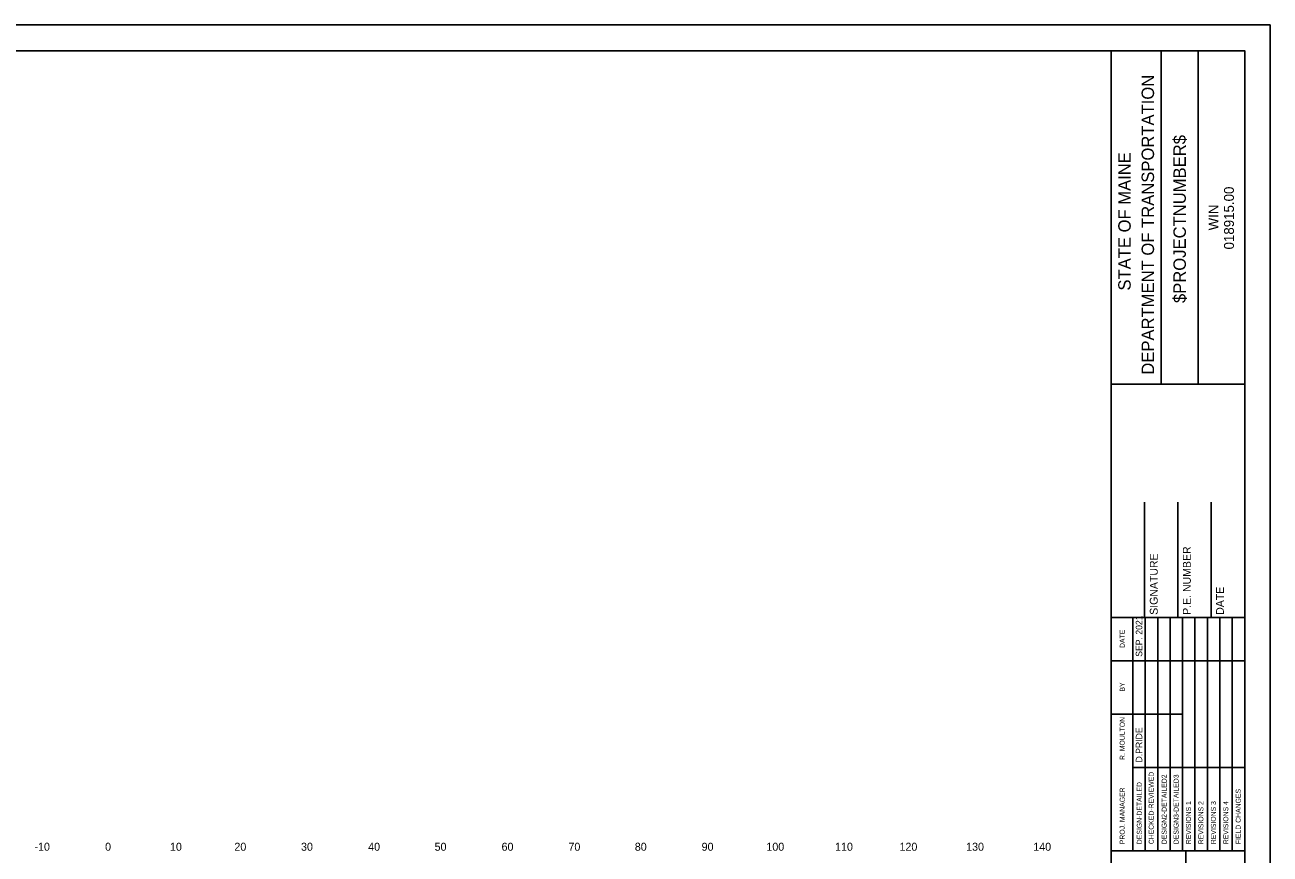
# Model space of a CAD drawing. Extents: x 1686373 to 1686716, y 461260 to 461480.
# Drawn here: x 1686526.3 to 1686713, y 461355.6 to 461480 of the extents above; entities that cross this region are included whole.
import ezdxf

# ---------------------------------------------------------------- set-up
doc = ezdxf.new("R2010")
doc.units = 0
for name, color, linetype in [('BORDER', 7, 'Continuous'), ('H_V ANNOTATION', 7, 'Continuous'), ('PLOT BOUNDARY', 7, 'Continuous')]:
    doc.layers.add(name, color=color, linetype=linetype)

msp = doc.modelspace()

# ---------------------------------------------------------------- linework, layer by layer
at = {"layer": 'BORDER'}
for p, q in [((1686689.17, 461266.07), (1686689.17, 461476.07)), ((1686696.63, 461426.07), (1686696.63, 461476.07)), ((1686702.22, 461426.07), (1686702.22, 461476.07)), ((1686689.17, 461426.06), (1686709.17, 461426.06)), ((1686694.17, 461391.08), (1686694.17, 461408.37)), ((1686699.17, 461391.08), (1686699.17, 461408.37)), ((1686704.17, 461391.08), (1686704.17, 461408.37)), ((1686689.17, 461391.08), (1686709.17, 461391.08)), ((1686689.17, 461356.08), (1686709.17, 461356.08)), ((1686700.35, 461286.08), (1686700.35, 461356.08))]:
    msp.add_line(p, q, dxfattribs=at)
msp.add_lwpolyline([(1686389.17, 461266.07), (1686709.17, 461266.07), (1686709.17, 461476.07), (1686389.17, 461476.07)], close=True, dxfattribs=at)
for points in [[(1686692.4, 461384.58), (1686692.4, 461391.08)], [(1686692.4, 461356.08), (1686692.4, 461389.67)], [(1686694.26, 461356.08), (1686694.26, 461391.08)], [(1686696.13, 461391.08), (1686696.13, 461356.08)], [(1686697.99, 461356.08), (1686697.99, 461391.08)], [(1686699.85, 461356.08), (1686699.85, 461391.08)], [(1686701.72, 461356.08), (1686701.72, 461391.08)], [(1686703.58, 461356.08), (1686703.58, 461391.08)], [(1686705.44, 461356.08), (1686705.44, 461391.08)], [(1686707.31, 461356.08), (1686707.31, 461391.08)], [(1686689.17, 461384.58), (1686709.17, 461384.58)], [(1686689.17, 461376.58), (1686692.4, 461376.58)], [(1686692.4, 461376.58), (1686699.85, 461376.58)], [(1686692.4, 461368.58), (1686709.17, 461368.58)]]:
    msp.add_lwpolyline(points, dxfattribs=at)
at = {"layer": 'PLOT BOUNDARY'}
msp.add_lwpolyline([(1686372.98, 461259.95), (1686712.98, 461259.95), (1686712.98, 461479.95), (1686372.98, 461479.95)], close=True, dxfattribs=at)

# ---------------------------------------------------------------- texts
at = {"layer": 'BORDER'}
for s, height, p in [('DEPARTMENT OF TRANSPORTATION', 1.8635, (1686695.58, 461427.48)), ('$PROJECTNUMBER$', 1.8635, (1686700.35, 461438.23)), ('STATE OF MAINE', 1.8635, (1686692.08, 461440.1)), ('018915.00', 1.491, (1686707.56, 461446.27)), ('WIN', 1.491, (1686705.24, 461449.13)), ('P.E. NUMBER', 1.1811, (1686701.09, 461391.46)), ('SIGNATURE', 1.181, (1686696.13, 461391.46)), ('DATE', 1.181, (1686706.05, 461391.46)), ('SEP. 2021', 0.969, (1686693.81, 461385.17)), ('DATE', 0.743, (1686691.18, 461386.49)), ('BY', 0.743, (1686691.18, 461379.95)), ('R. MOULTON', 0.745, (1686691.18, 461369.68)), ('D.PRIDE', 0.969, (1686693.81, 461369.32)), ('CHECKED-REVIEWED', 0.7455, (1686695.53, 461357.05)), ('DESIGN2-DETAILED2', 0.7455, (1686697.47, 461357.05)), ('DESIGN3-DETAILED3', 0.7455, (1686699.26, 461357.05)), ('PROJ. MANAGER', 0.7455, (1686691.18, 461357.05)), ('DESIGN-DETAILED', 0.7455, (1686693.74, 461357.05)), ('FIELD CHANGES', 0.7455, (1686708.57, 461357.05)), ('REVISIONS 1', 0.7455, (1686701.12, 461357.05)), ('REVISIONS 2', 0.7455, (1686702.98, 461357.05)), ('REVISIONS 3', 0.7455, (1686704.85, 461357.05)), ('REVISIONS 4', 0.7455, (1686706.71, 461357.05))]:
    msp.add_text(s, height=height, rotation=90, dxfattribs=at).set_placement(p)
at = {"layer": 'H_V ANNOTATION'}
for s, p in [('-10', (1686527.7, 461356.07)), ('0', (1686538.29, 461356.07)), ('10', (1686548.02, 461356.07)), ('20', (1686557.68, 461356.07)), ('30', (1686567.67, 461356.07)), ('40', (1686577.74, 461356.07)), ('50', (1686587.7, 461356.07)), ('60', (1686597.74, 461356.07)), ('70', (1686607.77, 461356.07)), ('80', (1686617.72, 461356.07)), ('90', (1686627.74, 461356.07)), ('100', (1686637.45, 461356.07)), ('110', (1686647.75, 461356.07)), ('120', (1686657.41, 461356.07)), ('130', (1686667.4, 461356.07)), ('140', (1686677.47, 461356.07))]:
    msp.add_text(s, height=1.2, dxfattribs=at).set_placement(p)

doc.saveas('drawing.dxf')
